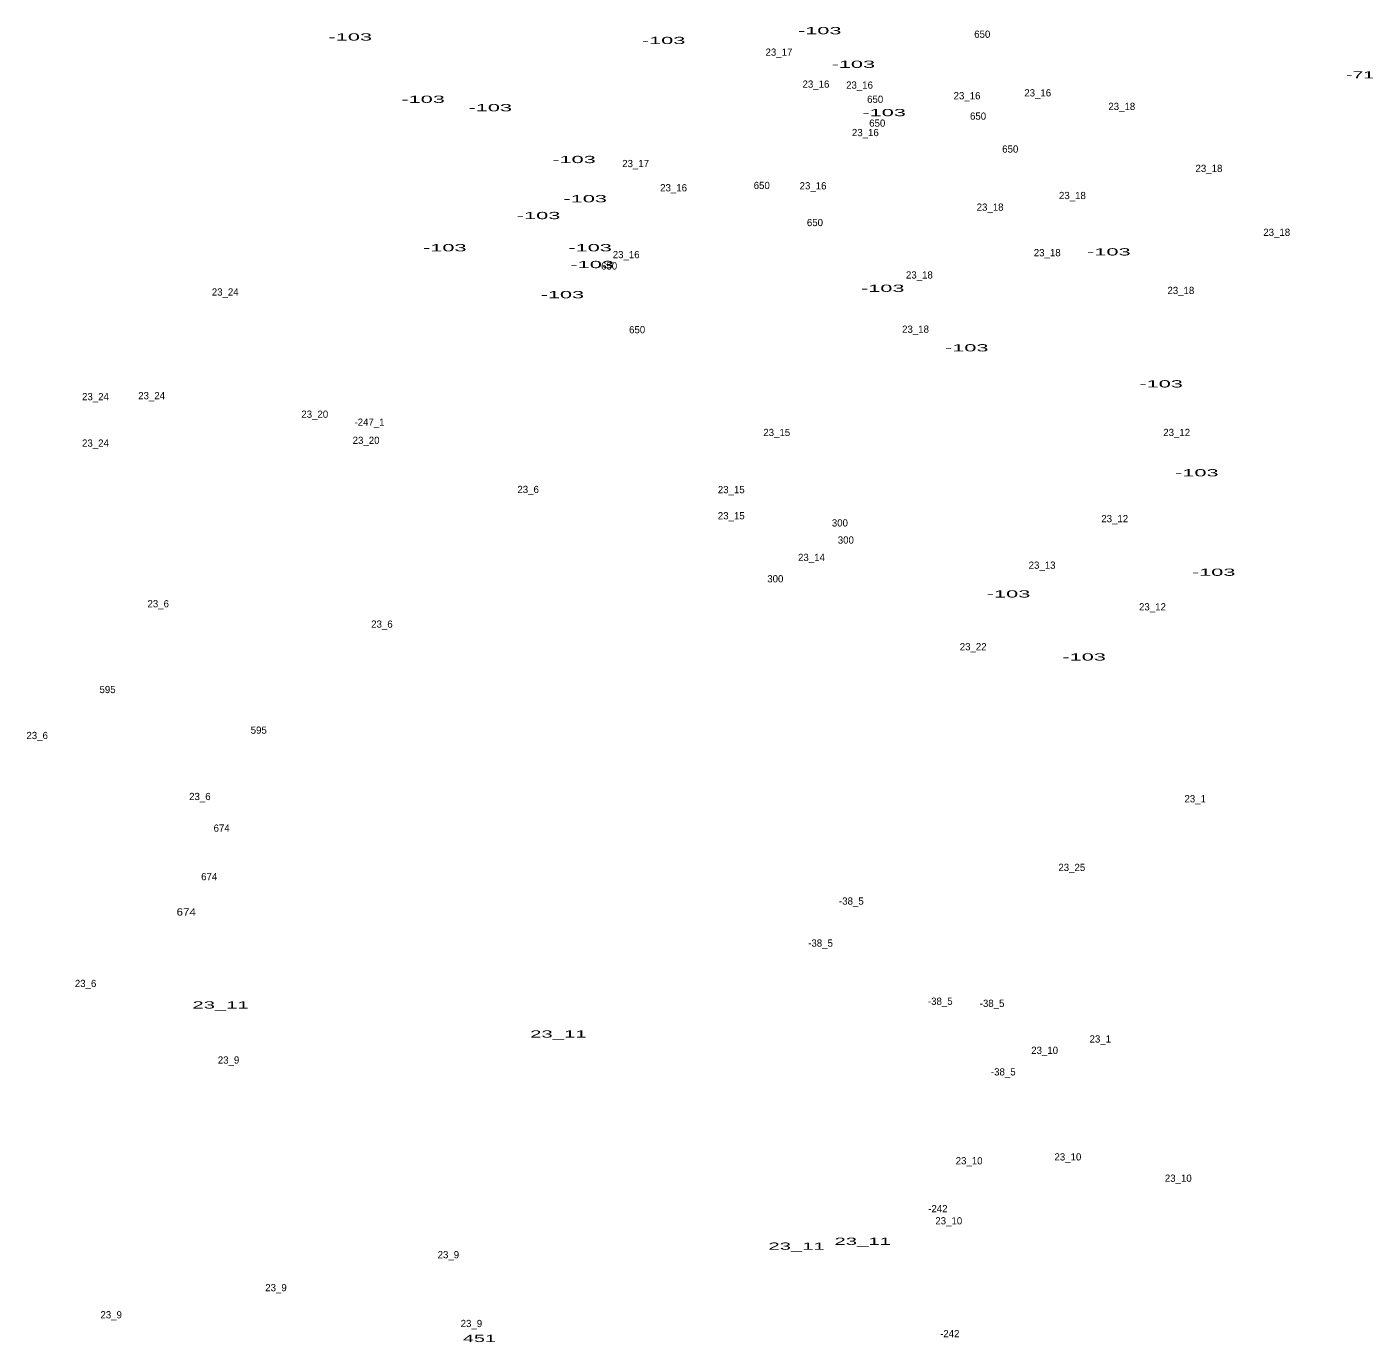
# Model space of a CAD drawing. Extents: x -661742 to -657295, y -1002932 to -996888.
# Drawn here: x -658789 to -658043, y -999838 to -999109 of the extents above; entities that cross this region are included whole.
import ezdxf
from ezdxf.enums import TextEntityAlignment as Align

# ---------------------------------------------------------------- set-up
doc = ezdxf.new("R2010")
doc.units = 0
doc.header["$LTSCALE"] = 1.6
doc.layers.add('24', color=7, linetype='Continuous')

msp = doc.modelspace()

# ---------------------------------------------------------------- texts
at = {"layer": '24'}
for s, width, p in [('-103', 2.25, (-658349.717, -999113.16)), ('-103', 2.25, (-658609.737, -999116.66)), ('-103', 2.25, (-658436.187, -999118.59)), ('-103', 2.25, (-658331.107, -999131.78)), ('-71', 2, (-658050.445, -999137.65)), ('-103', 2.25, (-658569.407, -999151.18)), ('-103', 2.25, (-658532.187, -999155.83)), ('-103', 2.25, (-658314.047, -999158.54)), ('-103', 2.25, (-658485.817, -999184.53)), ('-103', 2.25, (-658479.607, -999206.25)), ('-103', 2.25, (-658505.437, -999215.57)), ('-103', 2.25, (-658557.387, -999233.41)), ('-103', 2.25, (-658476.897, -999233.4)), ('-103', 2.25, (-658189.587, -999235.7)), ('-103', 2.25, (-658475.737, -999242.71)), ('-103', 2.25, (-658314.827, -999255.87)), ('-103', 2.25, (-658492.257, -999259.4)), ('-103', 2.25, (-658268.297, -999288.84)), ('-103', 2.25, (-658160.617, -999308.81)), ('-103', 2.25, (-658140.857, -999358.07)), ('-103', 2.25, (-658131.537, -999413.15)), ('-103', 2.25, (-658245.147, -999425.17)), ('-103', 2.25, (-658203.267, -999460.08)), ('674', 1.2, (-658700.581, -999601.33)), ('23_11', 2.1, (-658681.555, -999652.84)), ('23_11', 2.1, (-658494.475, -999668.94)), ('23_11', 2.1, (-658325.945, -999783.76)), ('23_11', 2.1, (-658362.525, -999786.45)), ('451', 2.05, (-658538.183, -999837.54))]:
    msp.add_text(s, height=4, dxfattribs=dict(at, width=width)).set_placement(p, align=Align.CENTER)
for s, p in [('650', (-658259.697, -999115.12)), ('23_17', (-658372.304, -999125.07)), ('23_16', (-658351.814, -999142.78)), ('23_16', (-658327.674, -999143.31)), ('650', (-658319.017, -999151.19)), ('23_16', (-658268.134, -999149.21)), ('23_16', (-658228.984, -999147.61)), ('23_18', (-658182.419, -999155.12)), ('650', (-658317.857, -999164.38)), ('650', (-658262.017, -999160.5)), ('23_16', (-658324.454, -999169.6)), ('650', (-658244.187, -999178.73)), ('23_17', (-658451.684, -999186.77)), ('23_18', (-658134.139, -999189.46)), ('23_16', (-658430.654, -999200.19)), ('650', (-658381.827, -999198.9)), ('23_16', (-658353.424, -999199.11)), ('23_18', (-658209.769, -999204.48)), ('23_18', (-658255.359, -999210.92)), ('650', (-658352.367, -999219.46)), ('23_18', (-658096.599, -999224.87)), ('23_16', (-658456.934, -999237.21)), ('23_18', (-658223.719, -999236.14)), ('650', (-658466.357, -999243.51)), ('23_18', (-658294.519, -999248.48)), ('23_24', (-658678.99, -999257.93)), ('23_18', (-658149.699, -999257.06)), ('650', (-658450.847, -999278.8)), ('23_18', (-658296.659, -999278.53)), ('23_24', (-658750.86, -999315.88)), ('23_24', (-658719.75, -999315.34)), ('23_20', (-658629.409, -999325.61)), ('-247_1', (-658599.086, -999330.03)), ('23_15', (-658373.519, -999335.73)), ('23_12', (-658152.009, -999335.73)), ('23_24', (-658750.86, -999341.63)), ('23_20', (-658600.979, -999340.1)), ('23_6', (-658511.21, -999367.3)), ('23_15', (-658398.729, -999367.39)), ('23_15', (-658398.729, -999381.88)), ('23_12', (-658186.329, -999383.49)), ('300', (-658338.545, -999385.83)), ('300', (-658335.255, -999395.31)), ('23_14', (-658354.303, -999404.95)), ('23_13', (-658226.559, -999409.24)), ('300', (-658374.325, -999416.79)), ('23_6', (-658716.1, -999430.61)), ('23_12', (-658165.419, -999432.31)), ('23_6', (-658592.2, -999441.88)), ('23_22', (-658264.725, -999454.42)), ('595', (-658744.173, -999478.13)), ('595', (-658660.423, -999500.63)), ('23_6', (-658783.15, -999503.58)), ('23_6', (-658693.04, -999537.38)), ('23_1', (-658141.749, -999538.61)), ('674', (-658680.973, -999554.88)), ('23_25', (-658210.105, -999576.65)), ('674', (-658687.853, -999581.74)), ('-38_5', (-658332.202, -999595.31)), ('-38_5', (-658349.262, -999618.58)), ('23_6', (-658756.33, -999640.94)), ('-38_5', (-658282.962, -999650.78)), ('-38_5', (-658254.262, -999651.94)), ('23_1', (-658194.309, -999671.67)), ('23_10', (-658225.143, -999677.98)), ('23_9', (-658677.15, -999683.35)), ('-38_5', (-658248.062, -999689.91)), ('23_10', (-658266.983, -999739.15)), ('23_10', (-658212.273, -999737)), ('23_10', (-658151.133, -999748.81)), ('-242', (-658284.269, -999765.67)), ('23_10', (-658278.243, -999772.41)), ('23_9', (-658555.4, -999791.2)), ('23_9', (-658650.87, -999809.44)), ('23_9', (-658742.16, -999824.47)), ('23_9', (-658542.64, -999829.29)), ('-242', (-658277.699, -999834.94))]:
    msp.add_text(s, height=4, dxfattribs=at).set_placement(p, align=Align.CENTER)

doc.saveas('drawing.dxf')
